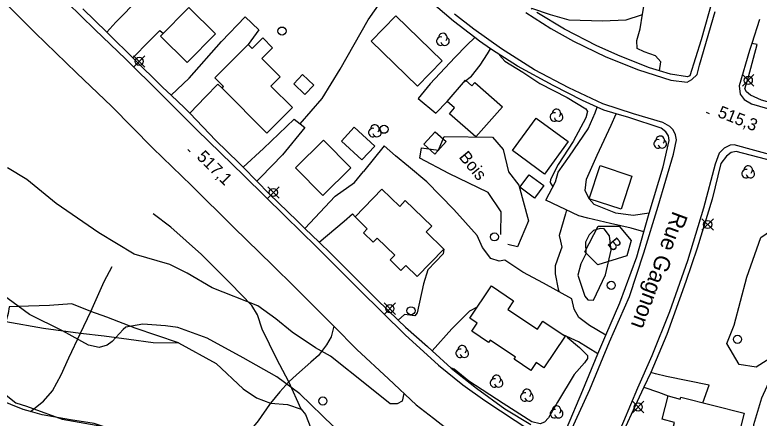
# Model space of a CAD drawing. Extents: x 347312 to 350503, y 6073086 to 6076432.
# Drawn here: x 348587.4 to 348771.6, y 6074425.4 to 6074525.1 of the extents above; entities that cross this region are included whole.
import ezdxf

# ---------------------------------------------------------------- set-up
doc = ezdxf.new("R2010")
doc.units = 0
for name, color, linetype in [('Level 19', 7, 'Continuous'), ('Level 2', 7, 'Continuous'), ('Level 21', 7, 'Continuous'), ('Level 22', 7, 'Continuous'), ('Level 3', 7, 'Continuous'), ('Level 31', 7, 'Continuous'), ('Level 36', 7, 'Continuous'), ('Level 44', 7, 'Continuous')]:
    doc.layers.add(name, color=color, linetype=linetype)

msp = doc.modelspace()

# ---------------------------------------------------------------- linework, layer by layer
at = {"layer": 'Level 19'}
for points in [[(348610.13, 6074520.9), (348612.35, 6074523.37), (348618.15, 6074529.3), (348619.17, 6074530.24), (348617.39, 6074532.25)], [(348746.94, 6074511.31), (348747.31, 6074513.57), (348745.96, 6074515), (348743.18, 6074515.99), (348741.45, 6074516.8), (348741.31, 6074518.78), (348742.15, 6074521.73), (348742.73, 6074525.35), (348743.41, 6074529.22), (348743.42, 6074532.67)], [(348626.03, 6074505.25), (348630.5, 6074509.53), (348638.49, 6074518.59), (348644.33, 6074524.65), (348647.78, 6074521.49), (348645.15, 6074517.8)], [(348616.52, 6074514.52), (348620.64, 6074518.67), (348623.25, 6074521.32), (348624.13, 6074520.56)], [(348701.2, 6074519.54), (348699.24, 6074517.67), (348696.31, 6074514.61), (348690.15, 6074508.13), (348690.15, 6074508.13), (348687.21, 6074504.45), (348691.55, 6074500.84), (348694.38, 6074503.75)], [(348698.69, 6074508.67), (348700.43, 6074509.98), (348702.55, 6074512.67), (348704.33, 6074515.5), (348705.12, 6074516.78)], [(348630.63, 6074500.82), (348634.58, 6074504.9), (348637.63, 6074508), (348638.65, 6074507.04)], [(348743.08, 6074471.5), (348739.97, 6074472.36), (348734.8, 6074473.53), (348729.24, 6074474.82), (348727, 6074475.44), (348727, 6074475.44), (348718.84, 6074479.31), (348721.21, 6074483.87), (348721.84, 6074486.23), (348724.68, 6074490.21), (348729.28, 6074496.95), (348731.06, 6074500.94), (348731.48, 6074502.35)], [(348744.39, 6074476.1), (348740.42, 6074475.56), (348736.14, 6074476.11), (348730.81, 6074478.21), (348729.52, 6074479.68), (348728.51, 6074481.71), (348728.84, 6074484.48), (348731.53, 6074490.45), (348734.96, 6074497.87), (348736.23, 6074500.67)], [(348643.85, 6074487.5), (348648.87, 6074492.1), (348656.5, 6074499.34), (348657.97, 6074498.18), (348659.1, 6074497.29), (348653.6, 6074490.55), (348648.22, 6074485.04), (348647.24, 6074484.02)], [(348733.67, 6074445.91), (348729.6, 6074448.3), (348726.99, 6074450.26), (348725.79, 6074452.35), (348725.28, 6074454.94), (348718.22, 6074458.75), (348713.11, 6074461.48), (348708.69, 6074464.43), (348708.69, 6074464.43), (348707.28, 6074464.23), (348705.17, 6074464.87), (348703.16, 6074467.57), (348701.83, 6074470.61), (348696.06, 6074477.02), (348689.38, 6074483.81), (348684.82, 6074487.68), (348681.61, 6074490.28), (348678.8, 6074492.76), (348673.7, 6074486.39)], [(348659.15, 6074472.33), (348666.63, 6074480.29), (348671.46, 6074483.68), (348673.7, 6074486.39)], [(348767.61, 6074405.52), (348768.93, 6074410.7), (348769.75, 6074418.56), (348770.34, 6074423.81), (348772.31, 6074430.38), (348776.32, 6074439.27), (348781.18, 6074449.85), (348784.3, 6074459.35), (348786.9, 6074469.69), (348789.29, 6074475.94), (348791.24, 6074483.88)], [(348662.68, 6074468.92), (348668.91, 6074474.15), (348670.94, 6074475.93), (348671.57, 6074475.17)], [(348693.54, 6074467.23), (348693.4, 6074466.02), (348689.63, 6074462.08), (348688.54, 6074458.6), (348686.98, 6074451.47), (348686.34, 6074450.7), (348683.83, 6074451.01), (348682.28, 6074449.63)], [(348690.66, 6074442.04), (348695.51, 6074447.48), (348699.98, 6074451.92), (348701.87, 6074452.91)], [(348731.68, 6074441.3), (348726.88, 6074444.29), (348723.08, 6074446.04)], [(348757.71, 6074429.19), (348759.21, 6074433.57), (348748.67, 6074435.66), (348745.95, 6074436.32), (348744.78, 6074436.72)], [(348743.1, 6074433.09), (348746.7, 6074431.82), (348749.07, 6074430.88)]]:
    msp.add_lwpolyline(points, dxfattribs=at)
at = {"layer": 'Level 2'}
for points in [[(348742.71, 6074525.23), (348742.38, 6074525.05), (348738.59, 6074523.87), (348732.84, 6074523.58), (348724.61, 6074523.88), (348719.94, 6074525.17), (348715.36, 6074526.73), (348715.21, 6074526.57)], [(348707.36, 6074515.3), (348707.32, 6074515.19), (348708.69, 6074513.71), (348713.09, 6074510.99), (348717.34, 6074508.15), (348724.07, 6074504.72), (348728.69, 6074501.92), (348729.14, 6074501.22)], [(348729.14, 6074501.22), (348728.71, 6074499.67), (348725.61, 6074493.85), (348721.87, 6074488.17), (348719.96, 6074484.43), (348719.9, 6074483.71), (348720.55, 6074482.61)], [(348683.66, 6074431.55), (348683.62, 6074431.5), (348683.21, 6074429.57), (348682.01, 6074428.94), (348680.29, 6074428.93), (348674.79, 6074433.3), (348665.51, 6074440.76), (348661.8, 6074442.79), (348656.04, 6074446.65), (348652, 6074449.98), (348647.49, 6074453.15), (348636.22, 6074457.59), (348629.99, 6074461.29), (348625.71, 6074463.37), (348616.85, 6074465.99), (348608.1, 6074471.27), (348597.55, 6074478.46), (348590.32, 6074484.44), (348585.5, 6074487.35)], [(348723.92, 6074476.9), (348723.66, 6074475.91), (348722.12, 6074470.61), (348722.43, 6074469.13), (348722.74, 6074467.65), (348722.08, 6074465.9), (348721.12, 6074463.08), (348721.09, 6074461.05), (348721.86, 6074457.29), (348722.12, 6074456.65)], [(348730.57, 6074454.57), (348733.58, 6074460.88), (348734.97, 6074466.96), (348734.59, 6074470.5), (348733.28, 6074472.26), (348732.22, 6074472.28), (348730.62, 6074471.77), (348729.51, 6074470.76), (348728.65, 6074468.9), (348728.69, 6074466.06), (348727.45, 6074463.58), (348726.74, 6074460.72), (348728.49, 6074455.54), (348729.23, 6074454.65), (348730.57, 6074454.57)], [(348672.16, 6074418.21), (348666.23, 6074423.36), (348657.88, 6074431.41), (348652.19, 6074435.64), (348643.87, 6074440.31), (348634.95, 6074445.16), (348627.72, 6074447.8), (348624.68, 6074448.2), (348619.03, 6074448.67), (348614.86, 6074447.9), (348614.15, 6074447.3), (348611.48, 6074444.37), (348610.21, 6074443.45), (348608.23, 6074442.85), (348605.58, 6074443.42), (348599.16, 6074446.98), (348590.94, 6074451.06), (348584.12, 6074456.1)], [(348724.05, 6074445.59), (348724.11, 6074445.42), (348727.16, 6074442.9), (348729.09, 6074440.92), (348729.09, 6074440.12), (348728.35, 6074439.1), (348725.86, 6074436.2), (348721.66, 6074429.32), (348719.45, 6074425.46), (348718.49, 6074424.38), (348717.37, 6074423.98), (348715.38, 6074424.44), (348708.23, 6074428.99), (348699.77, 6074434.56), (348696.08, 6074437.53), (348695.28, 6074437.82)], [(348584.81, 6074431.43), (348587.61, 6074429.15), (348590.25, 6074428.33), (348599.04, 6074425.1), (348608.91, 6074423.38), (348613.84, 6074422.89), (348616.31, 6074422.08)]]:
    msp.add_lwpolyline(points, dxfattribs=at)
at = {"layer": 'Level 21'}
for points in [[(348582.31, 6074530.75), (348592.37, 6074520.72), (348602.6, 6074510.85), (348611.33, 6074502.51), (348621.48, 6074492.19), (348631.11, 6074482.96), (348641.46, 6074472.67), (348651.22, 6074463.17), (348656.57, 6074457.91), (348666.31, 6074448.18), (348672.01, 6074442.39), (348679.84, 6074435.14), (348686.67, 6074428.72), (348690.99, 6074425.36), (348695.97, 6074421.5)], [(348600.42, 6074528.14), (348607.13, 6074521.51), (348614.8, 6074514.18), (348623.39, 6074505.73), (348632.38, 6074496.72), (348644.11, 6074485.31), (348654.24, 6074475.37), (348661.99, 6074467.75), (348672.71, 6074457.1), (348683.96, 6074446), (348692.25, 6074438.46), (348698.24, 6074433.67), (348703.7, 6074429.72), (348715.09, 6074422.23)], [(348724.86, 6074421.84), (348729.68, 6074432.46), (348734.6, 6074444.23), (348739.51, 6074455.47), (348743.08, 6074466.25), (348746.63, 6074477.87), (348750.38, 6074490.7), (348751.14, 6074494.21), (348750.89, 6074495.51), (348750.3, 6074496.68), (348749.51, 6074497.53), (348747.8, 6074498.51), (348740.51, 6074500.71), (348732.92, 6074503.17), (348724.48, 6074507.12), (348716.04, 6074511.52), (348707.83, 6074516.72), (348700.94, 6074521.6), (348696.23, 6074525.29)], [(348713.88, 6074525.73), (348720.08, 6074521.78), (348725.69, 6074518.63), (348733.68, 6074514.77), (348741.74, 6074511.55), (348749.73, 6074508.97), (348753.81, 6074508.47), (348754.94, 6074509.19), (348756.31, 6074510.42), (348756.88, 6074512.72), (348760.75, 6074525.96)], [(348771.69, 6074524.03), (348769.78, 6074518.09), (348769.21, 6074516.34), (348766.68, 6074507.56), (348766.95, 6074505.51), (348767.89, 6074504.19), (348769.76, 6074503.11), (348780.99, 6074499.86)], [(348776.57, 6074489.92), (348765.4, 6074493.01), (348764.45, 6074492.89), (348762.92, 6074492.21), (348761.75, 6074490.91), (348760.69, 6074488.21), (348757.81, 6074477.32), (348753.84, 6074464.3), (348749.41, 6074451.66), (348745.07, 6074440.83), (348741.46, 6074432.81), (348738.03, 6074424.56), (348735.35, 6074418.23), (348734.71, 6074415.57), (348735.15, 6074414.05), (348735.94, 6074412.91), (348737.16, 6074411.9), (348738.34, 6074411.51)]]:
    msp.add_lwpolyline(points, dxfattribs=at)
at = {"layer": 'Level 22'}
for points in [[(348657.97, 6074498.18), (348663.42, 6074504.43), (348667.9, 6074511.68), (348674.85, 6074523.89), (348679.54, 6074530.7), (348683.7, 6074534.39)], [(348727.95, 6074432.34), (348731.68, 6074441.3), (348733.67, 6074445.91), (348737.12, 6074453.88), (348741.31, 6074465.27), (348743.08, 6074471.5), (348744.39, 6074476.1), (348747.82, 6074487.6), (348749.37, 6074494.05), (348749.19, 6074495.26), (348748.54, 6074496.22), (348747.35, 6074497.11), (348739.33, 6074499.74), (348736.23, 6074500.67), (348733.15, 6074501.59), (348731.48, 6074502.35), (348727.85, 6074504.01), (348720.61, 6074507.68), (348711.83, 6074512.48), (348706.49, 6074515.86), (348705.12, 6074516.78), (348702.39, 6074518.62), (348701.2, 6074519.54), (348695.96, 6074523.58), (348689.88, 6074528.83)], [(348760.13, 6074529.26), (348757.26, 6074518.98), (348754.47, 6074510.05), (348753.87, 6074509.8)], [(348604.2, 6074526.65), (348610.13, 6074520.9), (348610.72, 6074520.32), (348616.52, 6074514.52), (348623.98, 6074507.17), (348626.03, 6074505.25), (348629.35, 6074502.15), (348630.63, 6074500.82), (348637.07, 6074494.11), (348642.8, 6074488.57), (348643.85, 6074487.5), (348647.24, 6074484.02), (348650.35, 6074480.84), (348657.21, 6074474.2), (348659.15, 6074472.33), (348662.68, 6074468.92), (348665.54, 6074466.16), (348677, 6074454.71), (348682.28, 6074449.63), (348684.09, 6074447.89), (348689.47, 6074443.12), (348690.66, 6074442.04), (348695.38, 6074437.73), (348701.64, 6074432.8), (348708.63, 6074427.72), (348715.11, 6074423.81)], [(348753.87, 6074509.8), (348749.63, 6074510.48), (348746.94, 6074511.31), (348744.5, 6074512.06), (348737.24, 6074514.95), (348731.45, 6074517.5), (348723.43, 6074521.58), (348716.56, 6074525.71)], [(348780.99, 6074499.86), (348781.78, 6074501.35), (348772.17, 6074504.08), (348769.46, 6074505.28), (348768.52, 6074506.15), (348768.05, 6074506.89), (348768.97, 6074509.86), (348771.14, 6074517.81), (348769.78, 6074518.09)], [(348775.12, 6074488.94), (348765.94, 6074491.35), (348764.7, 6074491.13), (348763.51, 6074490.21)], [(348763.51, 6074490.21), (348762.17, 6074488.4), (348759.96, 6074479.59), (348756.31, 6074467.45), (348753.5, 6074459.19), (348748.74, 6074446.05), (348744.78, 6074436.72), (348743.1, 6074433.09), (348741.94, 6074430.59), (348737.05, 6074420.05), (348736.15, 6074415.82), (348736.64, 6074414.42), (348737.66, 6074413.46), (348741.16, 6074412.03), (348751.85, 6074408.64), (348760.52, 6074406.58), (348767.61, 6074405.52), (348775.69, 6074404.54)], [(348658.24, 6074427.62), (348655.2, 6074434.38), (348652.17, 6074440.01), (348648.6, 6074447.37), (348647.44, 6074450.94), (348646.04, 6074453.25), (348640.75, 6074458.71), (348633.52, 6074465.87), (348625.97, 6074472.62), (348621.59, 6074475.9)], [(348591.23, 6074427.01), (348594.45, 6074429.57), (348596.65, 6074432.17), (348598.8, 6074436.11), (348600.72, 6074440.3), (348603.59, 6074446.44), (348606.14, 6074451.77), (348609.45, 6074459.18), (348611.46, 6074462.91)], [(348553.05, 6074458.96), (348561.86, 6074455.44), (348571.86, 6074452.38), (348578.89, 6074450.62), (348585.11, 6074449.32), (348594.43, 6074447.68), (348603.59, 6074446.44), (348609.48, 6074445.78), (348615.55, 6074444.89), (348621.59, 6074444.14), (348627.89, 6074443.98), (348637.21, 6074438.92), (348643.84, 6074432.67), (348647.16, 6074430.39), (348650.62, 6074429.1), (348654.86, 6074428.8), (348658.24, 6074427.62), (348659.31, 6074426.25), (348660.61, 6074422.87), (348661.54, 6074419.61)], [(348627.89, 6074443.98), (348617.14, 6074447.68), (348610.08, 6074450.38), (348606.14, 6074451.77), (348601.43, 6074453.64), (348595.95, 6074453.28), (348588.13, 6074453), (348585.91, 6074452.95), (348585.73, 6074451.28), (348585.11, 6074449.32), (348583, 6074445.42), (348579.84, 6074440.72), (348578.8, 6074436.72), (348579.09, 6074433.31)], [(348666.31, 6074448.18), (348665.67, 6074445.52), (348664.51, 6074443.49), (348662.56, 6074440.87), (348660.62, 6074439.23), (348657.07, 6074436.1), (348655.2, 6074434.38), (348652.98, 6074431.9), (348650.62, 6074429.1), (348650.37, 6074428.8), (348647.6, 6074424.72), (348642.46, 6074418.51), (348640.69, 6074415.65), (348640.2, 6074414.26), (348641.49, 6074409.27), (348644.01, 6074406.69), (348645.88, 6074403.64), (348646.81, 6074402.15)], [(348641.49, 6074409.27), (348636.12, 6074412.56), (348632.19, 6074413.13), (348628.7, 6074414.06), (348624.82, 6074415.2), (348622.1, 6074415.57), (348619.73, 6074416.61), (348615.41, 6074420.26), (348611.42, 6074422.61), (348606.99, 6074424.04), (348601.16, 6074424.98), (348594.09, 6074426.24), (348591.23, 6074427.01), (348589.43, 6074427.49), (348583.24, 6074430.04), (348579.09, 6074433.31), (348570.48, 6074438.3), (348566.64, 6074440.47), (348564.85, 6074440.18), (348563.11, 6074440.01), (348560.91, 6074442.19), (348559.56, 6074442.73)], [(348723.96, 6074422.71), (348727.95, 6074432.34)]]:
    msp.add_lwpolyline(points, dxfattribs=at)
at = {"layer": 'Level 3'}
for p, q in [((348758.49, 6074501.07), (348759.23, 6074500.77)), ((348630.18, 6074491.87), (348630.75, 6074491.3))]:
    msp.add_line(p, q, dxfattribs=at)
at = {"layer": 'Level 31'}
for points in [[(348630.45, 6074526.98), (348637.03, 6074520.5), (348630.01, 6074513.38), (348623.44, 6074519.86), (348630.45, 6074526.98)], [(348687.03, 6074507.54), (348675.59, 6074518.64), (348681.67, 6074524.91), (348693.11, 6074513.81), (348687.03, 6074507.54)], [(348649.76, 6074495.9), (348638.65, 6074507.04), (348639.02, 6074507.41), (348636.89, 6074509.55), (348645.15, 6074517.8), (348646.1, 6074516.85), (348648.72, 6074519.46), (348651.16, 6074517.01), (348648.51, 6074514.37), (348653.03, 6074509.85), (348650.73, 6074507.55), (348656.07, 6074502.2), (348649.76, 6074495.9)], [(348658.6, 6074510.39), (348661.36, 6074507.79), (348659.18, 6074505.49), (348656.43, 6074508.08), (348658.6, 6074510.39)], [(348701.49, 6074494.94), (348694.95, 6074500.67), (348696.23, 6074502.13), (348694.38, 6074503.75), (348698.94, 6074508.96), (348700.48, 6074507.6), (348701.21, 6074508.44), (348708.06, 6074502.44), (348701.49, 6074494.94)], [(348716.4, 6074499.64), (348724.36, 6074493.82), (348718.48, 6074485.78), (348710.52, 6074491.6), (348716.4, 6074499.64)], [(348673.28, 6074489.28), (348668.22, 6074493.93), (348671.37, 6074497.36), (348676.43, 6074492.71), (348673.28, 6074489.28)], [(348688.62, 6074493.13), (348691.42, 6074496.24), (348694.1, 6074493.84), (348691.29, 6074490.72), (348688.62, 6074493.13)], [(348663.59, 6074480.47), (348656.85, 6074487.33), (348663.79, 6074494.15), (348670.53, 6074487.3), (348663.59, 6074480.47)], [(348732.22, 6074487.88), (348740.13, 6074485.27), (348737.42, 6074477.07), (348729.52, 6074479.68), (348732.22, 6074487.88)], [(348712.4, 6074482.49), (348714.68, 6074485.61), (348718.32, 6074482.96), (348716.04, 6074479.84), (348712.4, 6074482.49)], [(348693.54, 6074467.23), (348686.97, 6074460.43), (348684.12, 6074463.18), (348682.93, 6074461.95), (348680.27, 6074464.52), (348681.42, 6074465.7), (348677.04, 6074469.92), (348676.04, 6074468.89), (348673.63, 6074471.22), (348674.61, 6074472.23), (348671.57, 6074475.17), (348678.21, 6074482.05), (348682.62, 6074477.78), (348684.02, 6074479.22), (348690.56, 6074472.9), (348689.17, 6074471.45), (348693.54, 6074467.23)], [(348705.05, 6074444.66), (348704.65, 6074444.07), (348700.45, 6074446.87), (348701.81, 6074448.91), (348700, 6074450.12), (348705.33, 6074458.09), (348710.79, 6074454.44), (348709.36, 6074452.3), (348716.73, 6074447.38), (348718.07, 6074449.39), (348723.59, 6074445.7), (348718.34, 6074437.85), (348716.43, 6074439.14), (348715.11, 6074437.17), (348710.96, 6074439.95), (348711.31, 6074440.47), (348705.05, 6074444.66)], [(348752.21, 6074430.58), (348767.88, 6074426.61), (348765.75, 6074418.2), (348750.1, 6074422.16), (348750.65, 6074424.35), (348747.61, 6074425.12), (348749.07, 6074430.88), (348752.1, 6074430.11), (348752.21, 6074430.58)]]:
    msp.add_lwpolyline(points, dxfattribs=at)
at = {"layer": 'Level 36'}
for p, q in [((348616.7, 6074512.24), (348619.52, 6074515.06)), ((348616.7, 6074515.06), (348619.52, 6074512.24)), ((348767.52, 6074507.54), (348770.34, 6074510.36)), ((348767.52, 6074510.36), (348770.34, 6074507.54)), ((348649.94, 6074479.81), (348652.76, 6074482.63)), ((348649.94, 6074482.63), (348652.76, 6074479.81)), ((348757.46, 6074471.88), (348760.28, 6074474.7)), ((348757.46, 6074474.7), (348760.28, 6074471.88)), ((348678.77, 6074451.06), (348681.59, 6074453.88)), ((348678.77, 6074453.88), (348681.59, 6074451.06)), ((348740.26, 6074426.73), (348743.08, 6074429.55)), ((348740.26, 6074429.55), (348743.08, 6074426.73))]:
    msp.add_line(p, q, dxfattribs=at)
for centre in [(348653.49, 6074521.15), (348618.11, 6074513.65), (348768.93, 6074508.95), (348678.75, 6074496.85), (348651.35, 6074481.22), (348758.87, 6074473.29), (348706.08, 6074470.23), (348735, 6074458.24), (348680.18, 6074452.47), (348685.42, 6074451.96), (348766.26, 6074444.89), (348663.61, 6074429.63), (348741.67, 6074428.14)]:
    msp.add_circle(centre, 1, dxfattribs=at)
at = {"layer": 'Level 44'}
for points in [[(348707.63, 6074470.79), (348707.72, 6074476.45), (348704.54, 6074481.18), (348694.75, 6074485.95), (348687.57, 6074489.73), (348688.03, 6074492.24), (348692.23, 6074491.69), (348693.6, 6074495.1), (348705.58, 6074494.9), (348708.26, 6074491.86), (348709.56, 6074486.32), (348712.13, 6074483.04), (348714.54, 6074474.19), (348711.77, 6074467.78), (348709.37, 6074468.33)], [(348786.48, 6074474.07), (348778.9, 6074451.24), (348775.2, 6074440.72), (348770.88, 6074437.99), (348766.7, 6074438.7), (348763.64, 6074443.83), (348765.43, 6074448.36), (348768.6, 6074460.24), (348772, 6074470.05), (348783.91, 6074478.25), (348786.46, 6074477.53), (348786.48, 6074474.07)], [(348728.47, 6074466.53), (348731.73, 6074472.89), (348736.96, 6074472.91), (348739.91, 6074469.35), (348738.84, 6074465.58), (348731.7, 6074463.35), (348728.47, 6074466.53)]]:
    msp.add_lwpolyline(points, dxfattribs=at)
for centre, start, end in [((348692.81, 6074518.65), 76.8848, 299.5691), ((348693.33, 6074519.55), 314.0633, 179.7519), ((348693.86, 6074518.65), 192.2171, 59.6742), ((348720.92, 6074499.88), 76.8848, 299.5691), ((348721.44, 6074500.78), 314.0633, 179.7519), ((348721.97, 6074499.88), 192.2171, 59.6742), ((348675.97, 6074496.04), 76.8848, 299.5691), ((348676.49, 6074496.94), 314.0633, 179.7519), ((348677.02, 6074496.04), 192.2171, 59.6742), ((348747.13, 6074494.14), 314.0633, 179.7519), ((348746.61, 6074493.24), 76.8848, 299.5691), ((348747.66, 6074493.24), 192.2171, 59.6742), ((348768.9, 6074486.76), 314.0633, 179.7519), ((348768.38, 6074485.86), 76.8848, 299.5691), ((348769.43, 6074485.86), 192.2171, 59.6742), ((348698.11, 6074442.34), 314.0633, 179.7519), ((348697.59, 6074441.44), 76.8848, 299.5691), ((348698.64, 6074441.44), 192.2171, 59.6742), ((348706.59, 6074435), 314.0633, 179.7519), ((348706.07, 6074434.1), 76.8848, 299.5691), ((348707.12, 6074434.1), 192.2171, 59.6742), ((348714.11, 6074431.53), 314.0633, 179.7519), ((348713.59, 6074430.63), 76.8848, 299.5691), ((348714.64, 6074430.63), 192.2171, 59.6742), ((348720.95, 6074426.48), 76.8848, 299.5691), ((348721.47, 6074427.38), 314.0633, 179.7519), ((348722, 6074426.48), 192.2171, 59.6742)]:
    msp.add_arc(centre, 1.05, start, end, dxfattribs=at)

# ---------------------------------------------------------------- texts
at = {"layer": 'Level 21'}
msp.add_text('Rue Gagnon', height=4, rotation=249.7162, dxfattribs=at).set_placement((348750.31, 6074476.8))
at = {"layer": 'Level 3'}
for s, rotation, p in [('515,3', 338.4839, (348761.15, 6074499.98)), ('517,1', 315.2921, (348632.2, 6074489.81))]:
    msp.add_text(s, height=3, rotation=rotation, dxfattribs=at).set_placement(p)
at = {"layer": 'Level 44'}
for s, p in [('Bois', (348697.14, 6074489.92)), ('B', (348733.87, 6074468.5))]:
    msp.add_text(s, height=3, rotation=309.568, dxfattribs=at).set_placement(p)

doc.saveas('drawing.dxf')
